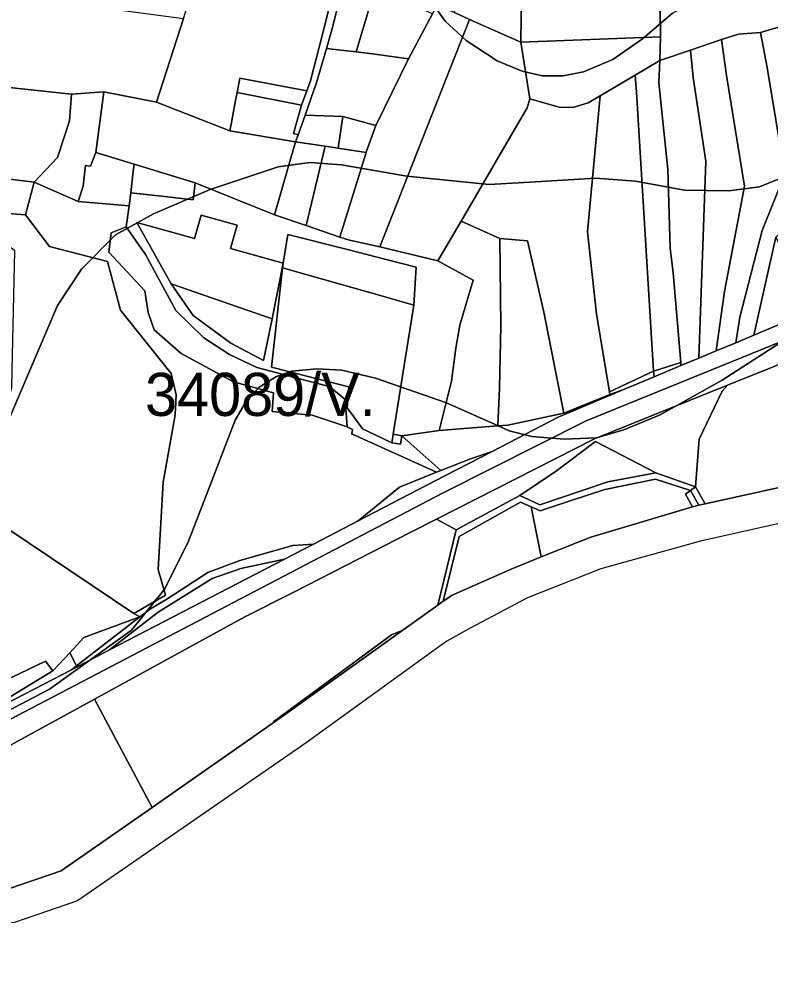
# Model space of a CAD drawing. Extents: x -535894 to -532827, y -1165802 to -1163635.
# Drawn here: x -534748.9 to -534487.4, y -1165568.7 to -1165239.1 of the extents above; entities that cross this region are included whole.
import ezdxf

# ---------------------------------------------------------------- set-up
doc = ezdxf.new("R2010")
doc.units = 0
for name, color, linetype in [('BPEJ_s', 7, 'Continuous'), ('orna_s', 7, 'Continuous'), ('ostatni_s', 7, 'Continuous'), ('sad_s', 7, 'Continuous'), ('trav_porost_s', 7, 'Continuous'), ('voda_s', 7, 'Continuous'), ('zahrada_s', 7, 'Continuous')]:
    doc.layers.add(name, color=color, linetype=linetype)

msp = doc.modelspace()

# ---------------------------------------------------------------- linework, layer by layer
at = {"layer": 'BPEJ_s'}
for points in [[(-534608.64, -1165167.21), (-534608.412, -1165173.45), (-534609.999, -1165183.45), (-534611.91, -1165195.48), (-534612.23, -1165202.72), (-534610.71, -1165215.87), (-534608.48, -1165224.47), (-534604.74, -1165233.86), (-534600.52, -1165239.92), (-534593.11, -1165246.69), (-534582.36, -1165253.77), (-534573.68, -1165257.329), (-534566.647, -1165258.95), (-534559.429, -1165258.95), (-534552.34, -1165257.6), (-534542.15, -1165253.22), (-534531.79, -1165246.05), (-534521.36, -1165237.13), (-534505.19, -1165228.05), (-534490.7, -1165221.44), (-534474.13, -1165216.26)], [(-534521.36, -1165237.13), (-534531.79, -1165246.05), (-534542.15, -1165253.22), (-534552.34, -1165257.6), (-534559.429, -1165258.95), (-534566.647, -1165258.95), (-534573.68, -1165257.329), (-534582.36, -1165253.77), (-534593.11, -1165246.69), (-534600.52, -1165239.92), (-534604.74, -1165233.86)], [(-534481.048, -1165293.523), (-534491.02, -1165297.58), (-534501.69, -1165299.01), (-534517.14, -1165298.69), (-534534.18, -1165295.66), (-534548.12, -1165294.571), (-534569.06, -1165295.82), (-534585.15, -1165296.78), (-534613.82, -1165293.91), (-534636.538, -1165289.974), (-534647.59, -1165289.13), (-534658.58, -1165290.571), (-534682.31, -1165298.53), (-534702.06, -1165306.97), (-534715.28, -1165314.3), (-534727.07, -1165326.25), (-534735.426, -1165338.913), (-534745.54, -1165362.56), (-534754.94, -1165384.54)], [(-534754.94, -1165384.54), (-534745.54, -1165362.56), (-534735.426, -1165338.913), (-534727.07, -1165326.25), (-534715.28, -1165314.3), (-534702.06, -1165306.97), (-534682.31, -1165298.53), (-534658.58, -1165290.571), (-534647.59, -1165289.13), (-534636.538, -1165289.974), (-534613.82, -1165293.91), (-534585.15, -1165296.78), (-534569.06, -1165295.82), (-534548.12, -1165294.571), (-534534.18, -1165295.66), (-534517.14, -1165298.69), (-534501.69, -1165299.01), (-534491.02, -1165297.58), (-534481.048, -1165293.523)], [(-534479.15, -1165348.82), (-534504, -1165364.91), (-534525.66, -1165376.94), (-534538.32, -1165382.19), (-534547.777, -1165384.87), (-534559.03, -1165385.38), (-534570.26, -1165384.5), (-534578.22, -1165382.43), (-534581.969, -1165380.76), (-534600.041, -1165372.71), (-534624.73, -1165364.11), (-534636.414, -1165361.355), (-534645.121, -1165360.93), (-534653.8, -1165361.72), (-534659.187, -1165363.557), (-534665.247, -1165367.305), (-534669.97, -1165372.64), (-534673.527, -1165378.814), (-534681.67, -1165399.87), (-534689.813, -1165420.926), (-534698.075, -1165437.459), (-534707.127, -1165448.709), (-534709.661, -1165451.859), (-534724.68, -1165462.63), (-534738.22, -1165472.34), (-534758.29, -1165482.861)], [(-534758.29, -1165482.861), (-534738.22, -1165472.34), (-534724.68, -1165462.63), (-534709.661, -1165451.859), (-534707.127, -1165448.709), (-534698.075, -1165437.459), (-534689.813, -1165420.926), (-534681.67, -1165399.87), (-534673.527, -1165378.814), (-534669.97, -1165372.64), (-534665.247, -1165367.305), (-534659.187, -1165363.557), (-534653.8, -1165361.72), (-534645.121, -1165360.93), (-534636.414, -1165361.355), (-534624.73, -1165364.11), (-534600.041, -1165372.71), (-534581.969, -1165380.76), (-534578.22, -1165382.43), (-534570.26, -1165384.5), (-534559.03, -1165385.38), (-534547.777, -1165384.87), (-534538.32, -1165382.19), (-534525.66, -1165376.94), (-534504, -1165364.91), (-534479.15, -1165348.82)], [(-534404.04, -1165396.72), (-534511.63, -1165420.88), (-534546.3, -1165430.52), (-534571.82, -1165440.57), (-534591.82, -1165451.2), (-534599.87, -1165455.71), (-534605.28, -1165459.52), (-534648.91, -1165491.07), (-534728.46, -1165546.03), (-534750.37, -1165553.57), (-534765.78, -1165554.79), (-534781.3, -1165555.36), (-534835.68, -1165558.38), (-534855.2, -1165560.47), (-534865.99, -1165562.72), (-534882.85, -1165568.74)]]:
    msp.add_lwpolyline(points, dxfattribs=at)
at = {"layer": 'orna_s'}
for points in [[(-534555.22, -1165133.48), (-534548.1, -1165130.49), (-534547.14, -1165136.27), (-534545.65, -1165145.14), (-534548.9, -1165148.28), (-534548.58, -1165157.34), (-534544.12, -1165157.18), (-534544.07, -1165158.63), (-534527.28, -1165157.93), (-534526.56, -1165167.24), (-534525.52, -1165245.33), (-534574.14, -1165247.28), (-534573.16, -1165174.91), (-534572.34, -1165142)], [(-534612.98, -1165209.1), (-534613.84, -1165233.07), (-534604.9, -1165237.35), (-534613.26, -1165253.08), (-534625.77, -1165251.25), (-534631.5, -1165250.59), (-534619.86, -1165211.52), (-534615.03, -1165209.82)], [(-534619.86, -1165211.52), (-534631.5, -1165250.59), (-534635.8, -1165250.1), (-534641.82, -1165249.4), (-534639.72, -1165242.1), (-534636.98, -1165231.14), (-534634.63, -1165222.23), (-534633.92, -1165220.53), (-534632.69, -1165217.6), (-534629.15, -1165214.48), (-534623.99, -1165212.98)], [(-534716.73, -1165313.55), (-534711.54, -1165311.45), (-534704.74, -1165321.13), (-534694.26, -1165340.63), (-534684.54, -1165350.12), (-534675.52, -1165355.92), (-534666.02, -1165360.45), (-534644.41, -1165366.09), (-534640.72, -1165367.06), (-534635.28, -1165371.61), (-534634.64, -1165381.14), (-534646.72, -1165376.99), (-534660.67, -1165375.77), (-534660.18, -1165369.23), (-534674.21, -1165365.47), (-534692.33, -1165355.62), (-534701.79, -1165347.3), (-534703.86, -1165341.25), (-534705.05, -1165333.73), (-534717.56, -1165320.29)]]:
    msp.add_lwpolyline(points, close=True, dxfattribs=at)
at = {"layer": 'ostatni_s'}
for points in [[(-534636.98, -1165231.14), (-534639.72, -1165242.1), (-534641.82, -1165249.4), (-534645.35, -1165261.71), (-534646.15, -1165263.94), (-534649.26, -1165272.62), (-534651.68, -1165279.51), (-534653.27, -1165279.03), (-534650.5, -1165269.13), (-534648.68, -1165264.17), (-534647.4, -1165260.65), (-534642.21, -1165240.82), (-534639.56, -1165229.81)], [(-534422.4, -1165326.53), (-534551.38, -1165379.05), (-534601.41, -1165404.16), (-534772.12, -1165493.42)], [(-534772.12, -1165493.42), (-534601.41, -1165404.16), (-534551.38, -1165379.05), (-534422.4, -1165326.53)], [(-534419.17, -1165333.25), (-534502.24, -1165366.65), (-534548.51, -1165385.26), (-534603.53, -1165413.28), (-534612.41, -1165417.8), (-534653.44, -1165438.69), (-534670.22, -1165447.23), (-534722.56, -1165475.88), (-534787.1, -1165511.18)], [(-534770.13, -1165486.11), (-534730.58, -1165465.6), (-534717.3, -1165458.7), (-534672.71, -1165435.57), (-534656.41, -1165427.11), (-534646.35, -1165421.89), (-534630.7, -1165413.78), (-534610.23, -1165403.15), (-534600.64, -1165398.18), (-534584.14, -1165389.62), (-534561.19, -1165377.71), (-534538.63, -1165368.27), (-534527.77, -1165363.73), (-534518.38, -1165359.8), (-534512.19, -1165357.2), (-534506.18, -1165354.68), (-534499.33, -1165351.82), (-534492.99, -1165349.16), (-534473.97, -1165341.2)]]:
    msp.add_lwpolyline(points, dxfattribs=at)
for points in [[(-534635.8, -1165250.1), (-534631.5, -1165250.59), (-534625.77, -1165251.25), (-534613.26, -1165253.08), (-534624.62, -1165276.23), (-534636.09, -1165273.14), (-534649.26, -1165272.62), (-534646.15, -1165263.94), (-534645.35, -1165261.71), (-534641.82, -1165249.4)], [(-534648.68, -1165264.17), (-534650.5, -1165269.13), (-534672.89, -1165264.71), (-534671.96, -1165259.81)], [(-534730.57, -1165265.33), (-534719.29, -1165264.53), (-534722.11, -1165285.6), (-534723.91, -1165290.37), (-534725.71, -1165290.16), (-534726.54, -1165297.31), (-534728.29, -1165302.64), (-534743.59, -1165295.91), (-534735.39, -1165287.4), (-534731.26, -1165274.58)], [(-534672.89, -1165264.71), (-534650.5, -1165269.13), (-534653.27, -1165279.03), (-534651.68, -1165279.51), (-534652.53, -1165281.94), (-534675.39, -1165278.09), (-534674.85, -1165275.19), (-534673.41, -1165267.52)], [(-534636.09, -1165273.14), (-534637.76, -1165284.12), (-534642.27, -1165283.46), (-534652.53, -1165281.94), (-534651.68, -1165279.51), (-534649.26, -1165272.62)], [(-534708.76, -1165289.69), (-534709.03, -1165292.09), (-534709.85, -1165299.65), (-534710.5, -1165304.17), (-534728.29, -1165302.64), (-534726.54, -1165297.31), (-534725.71, -1165290.16), (-534723.91, -1165290.37), (-534722.11, -1165285.6)], [(-534709.03, -1165292.09), (-534708.76, -1165289.69), (-534687.53, -1165296.2), (-534688.22, -1165302.15), (-534698.22, -1165300.99), (-534709.85, -1165299.65)]]:
    msp.add_lwpolyline(points, close=True, dxfattribs=at)
at = {"layer": 'sad_s'}
msp.add_lwpolyline([(-534526.42, -1165144.06), (-534506.66, -1165142.89), (-534505.88, -1165150.21), (-534486.55, -1165149.95), (-534482.37, -1165149.5), (-534479.49, -1165178.1), (-534474.69, -1165217.27), (-534470.72, -1165237.94), (-534490.64, -1165243.85), (-534498.4, -1165244.45), (-534504.24, -1165246.32), (-534515.07, -1165249.99), (-534525.69, -1165253.61), (-534525.52, -1165245.33), (-534526.56, -1165167.24), (-534526.49, -1165154.6)], close=True, dxfattribs=at)
at = {"layer": 'trav_porost_s'}
for points in [[(-534635.35, -1165216.23), (-534636.93, -1165221.04), (-534639.56, -1165229.81), (-534642.21, -1165240.82), (-534647.4, -1165260.65), (-534648.68, -1165264.17), (-534671.96, -1165259.81), (-534672.89, -1165264.71), (-534673.41, -1165267.52), (-534674.85, -1165275.19), (-534675.39, -1165278.09), (-534700.96, -1165268.14), (-534691.61, -1165239), (-534688.84, -1165230.36), (-534686.31, -1165229.5), (-534683.94, -1165228.77), (-534634.06, -1165213.3)], [(-534470.72, -1165237.94), (-534472.13, -1165251.45), (-534468.11, -1165285.65), (-534468.02, -1165297.74), (-534474.75, -1165304.46), (-534485.35, -1165315.07), (-534492.99, -1165349.16), (-534499.33, -1165351.82), (-534497.87, -1165342.96), (-534490.1, -1165312.82), (-534482.19, -1165293.14), (-534488.32, -1165256.04), (-534490.64, -1165243.85)], [(-534591.99, -1165239.3), (-534574.14, -1165247.28), (-534570.97, -1165266.95), (-534571.87, -1165270.05), (-534594.9, -1165309.5), (-534602.97, -1165323.34), (-534620.31, -1165319.14), (-534623.17, -1165318.51)], [(-534490.64, -1165243.85), (-534488.32, -1165256.04), (-534482.19, -1165293.14), (-534490.1, -1165312.82), (-534497.87, -1165342.96), (-534499.33, -1165351.82), (-534506.18, -1165354.68), (-534503.19, -1165333.95), (-534496.27, -1165297.39), (-534502.48, -1165258.78), (-534504.24, -1165246.32), (-534498.4, -1165244.45)], [(-534504.24, -1165246.32), (-534502.48, -1165258.78), (-534496.27, -1165297.39), (-534503.19, -1165333.95), (-534506.18, -1165354.68), (-534512.19, -1165357.2), (-534509.72, -1165288.59), (-534514.18, -1165259.48), (-534515.07, -1165249.99)], [(-534515.07, -1165249.99), (-534514.18, -1165259.48), (-534509.72, -1165288.59), (-534512.19, -1165357.2), (-534518.38, -1165359.8), (-534518.48, -1165358.66), (-534521.1, -1165327.5), (-534522.16, -1165318.88), (-534522.93, -1165291.48), (-534526.11, -1165261.43), (-534525.69, -1165253.61)], [(-534525.69, -1165253.61), (-534526.11, -1165261.43), (-534522.93, -1165291.48), (-534522.16, -1165318.88), (-534521.1, -1165327.5), (-534518.48, -1165358.66), (-534527.9, -1165361.77), (-534533.9, -1165264.67), (-534534.27, -1165258.67)], [(-534533.9, -1165264.67), (-534527.9, -1165361.77), (-534543.25, -1165368.91), (-534547.76, -1165341.88), (-534550.89, -1165313.21), (-534546.51, -1165265.89), (-534534.27, -1165258.67)], [(-534719.29, -1165264.53), (-534700.96, -1165268.14), (-534675.39, -1165278.09), (-534652.53, -1165281.94), (-534659.83, -1165307.34), (-534687.53, -1165296.2), (-534708.76, -1165289.69), (-534722.11, -1165285.6)], [(-534546.51, -1165265.89), (-534550.89, -1165313.21), (-534547.76, -1165341.88), (-534543.25, -1165368.91), (-534543.11, -1165369.79), (-534559.18, -1165376.29), (-534566.14, -1165341.15), (-534571.85, -1165316.34), (-534581.4, -1165315.61), (-534594.9, -1165309.5), (-534571.87, -1165270.05), (-534570.97, -1165266.95), (-534560.78, -1165269.82), (-534556, -1165269.92), (-534550.66, -1165268.35)], [(-534764.53, -1165293.41), (-534754.18, -1165306.73), (-534746.57, -1165307.35), (-534738.25, -1165318.32), (-534717.97, -1165323.6), (-534713.44, -1165340.52), (-534695.84, -1165362.52), (-534694.17, -1165369.98), (-534694.4, -1165374.89), (-534694.53, -1165377.59), (-534698.61, -1165400.31), (-534700.33, -1165430.79), (-534697.82, -1165439.67), (-534708.8, -1165446.03), (-534774.44, -1165402.06), (-534773.37, -1165397.58), (-534762.44, -1165404.62), (-534756.01, -1165383.07), (-534751.34, -1165367.38), (-534751.2, -1165361.26), (-534750.26, -1165319.8), (-534758.59, -1165313.74), (-534764.1, -1165305.72)], [(-534743.59, -1165295.91), (-534746.57, -1165307.35), (-534754.18, -1165306.73), (-534764.53, -1165293.41)], [(-534743.59, -1165295.91), (-534728.29, -1165302.64), (-534710.5, -1165304.17), (-534711.54, -1165311.45), (-534716.73, -1165313.55), (-534717.56, -1165320.29), (-534705.05, -1165333.73), (-534703.86, -1165341.25), (-534701.79, -1165347.3), (-534692.33, -1165355.62), (-534674.21, -1165365.47), (-534660.18, -1165369.23), (-534660.67, -1165375.77), (-534646.72, -1165376.99), (-534634.64, -1165381.14), (-534632.69, -1165381.98), (-534632.99, -1165383.48), (-534633.02, -1165383.62), (-534632.47, -1165383.72), (-534603.43, -1165396.91), (-534616.38, -1165402.05), (-534630.7, -1165413.78), (-534646.35, -1165421.89), (-534653.45, -1165422.42), (-534671.92, -1165427.59), (-534683.04, -1165431.83), (-534697.42, -1165441.07), (-534703.07, -1165444.48), (-534706.72, -1165447.2), (-534708.8, -1165446.03), (-534697.82, -1165439.67), (-534700.33, -1165430.79), (-534698.61, -1165400.31), (-534694.53, -1165377.59), (-534694.4, -1165374.89), (-534694.17, -1165369.98), (-534695.84, -1165362.52), (-534713.44, -1165340.52), (-534717.97, -1165323.6), (-534738.25, -1165318.32), (-534746.57, -1165307.35)], [(-534660.74, -1165343.46), (-534656.86, -1165324.17), (-534657.11, -1165325.73), (-534660.93, -1165360.38), (-534644.09, -1165364.61), (-534633.99, -1165367.14), (-534634.54, -1165374.52), (-534631.93, -1165378.09), (-534629.25, -1165381.75), (-534622.61, -1165384.94), (-534619.01, -1165386.65), (-534616.04, -1165387.12), (-534615.57, -1165384.17), (-534601.97, -1165396.33), (-534603.43, -1165396.91), (-534632.47, -1165383.72), (-534633.02, -1165383.62), (-534632.99, -1165383.48), (-534632.69, -1165381.98), (-534634.64, -1165381.14), (-534635.28, -1165371.61), (-534640.72, -1165367.06), (-534644.41, -1165366.09), (-534666.02, -1165360.45), (-534675.52, -1165355.92), (-534684.54, -1165350.12), (-534694.26, -1165340.63), (-534704.74, -1165321.13), (-534711.54, -1165311.45), (-534710.5, -1165304.17), (-534709.85, -1165299.65), (-534698.22, -1165300.99), (-534688.22, -1165302.15), (-534687.53, -1165296.2), (-534659.83, -1165307.34), (-534648.89, -1165311.07), (-534637.1, -1165315.06), (-534633.83, -1165316.18), (-534623.17, -1165318.51), (-534620.31, -1165319.14), (-534602.97, -1165323.34), (-534590.76, -1165330.1), (-534595.37, -1165345.7), (-534596.74, -1165353.72), (-534598.25, -1165365.19), (-534602.56, -1165382.4), (-534615.57, -1165384.17), (-534618.54, -1165383.7), (-534611.39, -1165338.79), (-534610.55, -1165325.54), (-534621.05, -1165322.85), (-534634.51, -1165319.42), (-534655.24, -1165314.11), (-534656.86, -1165324.17), (-534675.18, -1165319.07), (-534672.89, -1165310.88), (-534685.42, -1165307.39), (-534687.7, -1165315.57), (-534707.83, -1165309.96), (-534695.88, -1165331.28), (-534688.17, -1165342.38), (-534675.04, -1165351.98), (-534663.67, -1165357.97)], [(-534581.4, -1165315.61), (-534581.07, -1165345.98), (-534581.57, -1165367.64), (-534582.11, -1165380.79), (-534602.56, -1165382.4), (-534598.25, -1165365.19), (-534596.74, -1165353.72), (-534595.37, -1165345.7), (-534590.76, -1165330.1), (-534602.97, -1165323.34), (-534594.9, -1165309.5)], [(-534655.24, -1165314.11), (-534634.51, -1165319.42), (-534621.05, -1165322.85), (-534610.55, -1165325.54), (-534611.39, -1165338.79), (-534623.5, -1165335.33), (-534637.06, -1165331.46), (-534657.11, -1165325.73), (-534656.86, -1165324.17)], [(-534571.85, -1165316.34), (-534566.14, -1165341.15), (-534559.18, -1165376.29), (-534578.69, -1165380.51), (-534582.11, -1165380.79), (-534581.57, -1165367.64), (-534581.07, -1165345.98), (-534581.4, -1165315.61)], [(-534485.35, -1165315.07), (-534473.17, -1165340.76), (-534473.97, -1165341.2), (-534492.99, -1165349.16)], [(-534637.06, -1165331.46), (-534623.5, -1165335.33), (-534611.39, -1165338.79), (-534618.54, -1165383.7), (-534618.67, -1165384.51), (-534619.01, -1165386.65), (-534622.61, -1165384.94), (-534629.25, -1165381.75), (-534631.93, -1165378.09), (-534634.54, -1165374.52), (-534633.99, -1165367.14), (-534644.09, -1165364.61), (-534660.93, -1165360.38), (-534657.11, -1165325.73)], [(-534364.65, -1165326.48), (-534360.45, -1165326.25), (-534347.57, -1165373.21), (-534350.42, -1165373.76), (-534406.37, -1165385.09), (-534509.97, -1165407.93), (-534513.35, -1165401.93), (-534512.04, -1165385.37), (-534503.99, -1165368.68), (-534502.24, -1165366.65), (-534419.17, -1165333.25)], [(-534518.48, -1165358.66), (-534518.38, -1165359.8), (-534527.77, -1165363.73), (-534527.9, -1165361.77)], [(-534527.77, -1165363.73), (-534538.63, -1165368.27), (-534543.11, -1165369.79), (-534543.25, -1165368.91), (-534527.9, -1165361.77)], [(-534502.24, -1165366.65), (-534503.99, -1165368.68), (-534512.04, -1165385.37), (-534513.35, -1165401.93), (-534527.13, -1165397.14), (-534548.14, -1165386.16), (-534561.68, -1165396.35), (-534574.43, -1165404.96), (-534596.68, -1165416.98), (-534603.53, -1165413.28), (-534548.51, -1165385.26)], [(-534543.11, -1165369.79), (-534538.63, -1165368.27), (-534561.19, -1165377.71), (-534584.14, -1165389.62), (-534591.66, -1165392.25), (-534601.97, -1165396.33), (-534615.57, -1165384.17), (-534602.56, -1165382.4), (-534582.11, -1165380.79), (-534578.69, -1165380.51), (-534559.18, -1165376.29)], [(-534615.57, -1165384.17), (-534616.04, -1165387.12), (-534619.01, -1165386.65), (-534618.67, -1165384.51), (-534618.54, -1165383.7)], [(-534561.68, -1165396.35), (-534548.14, -1165386.16), (-534527.13, -1165397.14), (-534543.84, -1165400.27), (-534567.46, -1165408.26), (-534574.43, -1165404.96)], [(-534591.66, -1165392.25), (-534584.14, -1165389.62), (-534600.64, -1165398.18), (-534610.23, -1165403.15), (-534630.7, -1165413.78), (-534616.38, -1165402.05), (-534603.43, -1165396.91), (-534601.97, -1165396.33)], [(-534527.13, -1165397.14), (-534513.35, -1165401.93), (-534515.05, -1165403.23), (-534527.22, -1165399.28), (-534544.87, -1165402.87), (-534557.01, -1165406.86), (-534567.43, -1165410.29), (-534570.57, -1165408.93), (-534574.28, -1165407.33), (-534595.62, -1165419.29), (-534601.13, -1165441.8), (-534603.02, -1165443.16), (-534596.68, -1165416.98), (-534574.43, -1165404.96), (-534567.46, -1165408.26), (-534543.84, -1165400.27)], [(-534777.14, -1165399.85), (-534774.44, -1165402.06), (-534708.8, -1165446.03), (-534706.72, -1165447.2), (-534726.22, -1165454.44), (-534731.16, -1165459.74), (-534737, -1165466.01), (-534739.65, -1165462.65), (-534768.94, -1165476.68), (-534769.67, -1165481.85), (-534779.55, -1165483.95), (-534797.58, -1165460.25), (-534800.02, -1165457.14), (-534797.86, -1165446.44), (-534791.04, -1165427.36), (-534790.14, -1165428.15), (-534783.92, -1165413.27)], [(-534544.87, -1165402.87), (-534527.22, -1165399.28), (-534515.05, -1165403.23), (-534516.77, -1165404.52), (-534514.4, -1165408.9), (-534549.73, -1165419.5), (-534554.75, -1165421.51), (-534567.01, -1165426.39), (-534570.57, -1165408.93), (-534567.43, -1165410.29), (-534557.01, -1165406.86)], [(-534515.05, -1165403.23), (-534512.18, -1165408.41), (-534514.4, -1165408.9), (-534516.77, -1165404.52)], [(-534513.35, -1165401.93), (-534509.97, -1165407.93), (-534512.18, -1165408.41), (-534515.05, -1165403.23)], [(-534574.28, -1165407.33), (-534570.57, -1165408.93), (-534567.01, -1165426.39), (-534577.5, -1165430.58), (-534598.29, -1165439.76), (-534599.24, -1165440.45), (-534601.13, -1165441.8), (-534595.62, -1165419.29)], [(-534596.68, -1165416.98), (-534603.02, -1165443.16), (-534615.22, -1165451.89), (-534619.17, -1165453.43), (-534660.1, -1165483.67), (-534660.38, -1165484.14), (-534702.49, -1165513.54), (-534722.56, -1165475.88), (-534670.22, -1165447.23), (-534653.44, -1165438.69), (-534612.41, -1165417.8), (-534603.53, -1165413.28)], [(-534653.45, -1165422.42), (-534646.35, -1165421.89), (-534656.41, -1165427.11), (-534671.6, -1165430.4), (-534681.64, -1165433.88), (-534700.4, -1165445.64), (-534717.3, -1165458.7), (-534730.58, -1165465.6), (-534728.78, -1165464.21), (-534706.72, -1165447.2), (-534703.07, -1165444.48), (-534697.42, -1165441.07), (-534683.04, -1165431.83), (-534671.92, -1165427.59)], [(-534671.6, -1165430.4), (-534656.41, -1165427.11), (-534672.71, -1165435.57), (-534717.3, -1165458.7), (-534700.4, -1165445.64), (-534681.64, -1165433.88)], [(-534726.22, -1165454.44), (-534706.72, -1165447.2), (-534728.78, -1165464.21), (-534731.16, -1165459.74)], [(-534619.17, -1165453.43), (-534615.22, -1165451.89), (-534656.83, -1165481.66), (-534660.38, -1165484.14), (-534660.1, -1165483.67)], [(-534728.78, -1165464.21), (-534730.58, -1165465.6), (-534770.13, -1165486.11), (-534737, -1165466.01), (-534731.16, -1165459.74)], [(-534739.65, -1165462.65), (-534737, -1165466.01), (-534770.13, -1165486.11), (-534775.01, -1165488.64), (-534779.55, -1165483.95), (-534769.67, -1165481.85), (-534768.94, -1165476.68)], [(-534787.1, -1165511.18), (-534722.56, -1165475.88), (-534702.49, -1165513.54), (-534734.15, -1165535.63), (-534752.11, -1165541.71), (-534767.34, -1165543.34), (-534781.05, -1165543.94), (-534792.57, -1165513.75)]]:
    msp.add_lwpolyline(points, close=True, dxfattribs=at)
at = {"layer": 'voda_s'}
for points in [[(-534752.11, -1165541.71), (-534734.15, -1165535.63), (-534702.49, -1165513.54), (-534660.38, -1165484.14), (-534656.83, -1165481.66), (-534615.22, -1165451.89), (-534603.02, -1165443.16), (-534601.13, -1165441.8), (-534599.24, -1165440.45), (-534598.29, -1165439.76), (-534577.5, -1165430.58), (-534567.01, -1165426.39), (-534554.75, -1165421.51), (-534549.73, -1165419.5), (-534514.4, -1165408.9), (-534512.18, -1165408.41), (-534509.97, -1165407.93), (-534406.37, -1165385.09)], [(-534404.04, -1165396.72), (-534511.63, -1165420.88), (-534546.3, -1165430.52), (-534571.82, -1165440.57), (-534591.82, -1165451.2), (-534599.87, -1165455.71), (-534605.28, -1165459.52), (-534648.91, -1165491.07), (-534728.46, -1165546.03), (-534750.37, -1165553.57)]]:
    msp.add_lwpolyline(points, dxfattribs=at)
at = {"layer": 'zahrada_s'}
for points in [[(-534587.22, -1165174.4), (-534584.13, -1165174.48), (-534573.16, -1165174.91), (-534574.14, -1165247.28), (-534591.99, -1165239.3), (-534597.25, -1165236.95)], [(-534761.05, -1165235.16), (-534721.27, -1165235.1), (-534691.61, -1165239), (-534700.96, -1165268.14), (-534719.29, -1165264.53), (-534730.57, -1165265.33), (-534763.18, -1165261.89)], [(-534603.26, -1165234.27), (-534597.25, -1165236.95), (-534591.99, -1165239.3), (-534623.17, -1165318.51), (-534633.83, -1165316.18), (-534637.1, -1165315.06), (-534627.97, -1165285.63), (-534627.83, -1165285.22), (-534624.62, -1165276.23), (-534613.26, -1165253.08), (-534604.9, -1165237.35)], [(-534574.14, -1165247.28), (-534525.52, -1165245.33), (-534525.69, -1165253.61), (-534534.27, -1165258.67), (-534546.51, -1165265.89), (-534550.66, -1165268.35), (-534556, -1165269.92), (-534560.78, -1165269.82), (-534570.97, -1165266.95)], [(-534802.51, -1165263.09), (-534763.18, -1165261.89), (-534730.57, -1165265.33), (-534731.26, -1165274.58), (-534735.39, -1165287.4), (-534743.59, -1165295.91), (-534764.53, -1165293.41), (-534773.21, -1165290.92), (-534801.69, -1165282.74), (-534810.47, -1165278.22)], [(-534624.62, -1165276.23), (-534627.83, -1165285.22), (-534627.97, -1165285.63), (-534637.76, -1165284.12), (-534636.09, -1165273.14)], [(-534652.53, -1165281.94), (-534642.27, -1165283.46), (-534648.89, -1165311.07), (-534659.83, -1165307.34)], [(-534642.27, -1165283.46), (-534637.76, -1165284.12), (-534627.97, -1165285.63), (-534637.1, -1165315.06), (-534648.89, -1165311.07)], [(-534672.89, -1165310.88), (-534675.18, -1165319.07), (-534656.86, -1165324.17), (-534660.74, -1165343.46), (-534695.88, -1165331.28), (-534707.83, -1165309.96), (-534687.7, -1165315.57), (-534685.42, -1165307.39)], [(-534688.17, -1165342.38), (-534695.88, -1165331.28), (-534660.74, -1165343.46), (-534663.67, -1165357.97), (-534675.04, -1165351.98)]]:
    msp.add_lwpolyline(points, close=True, dxfattribs=at)

# ---------------------------------------------------------------- texts
at = {"layer": 'BPEJ_s'}
msp.add_text('34089/V.', height=15, dxfattribs=at).set_placement((-534704.965, -1165377.301))

doc.saveas('drawing.dxf')
